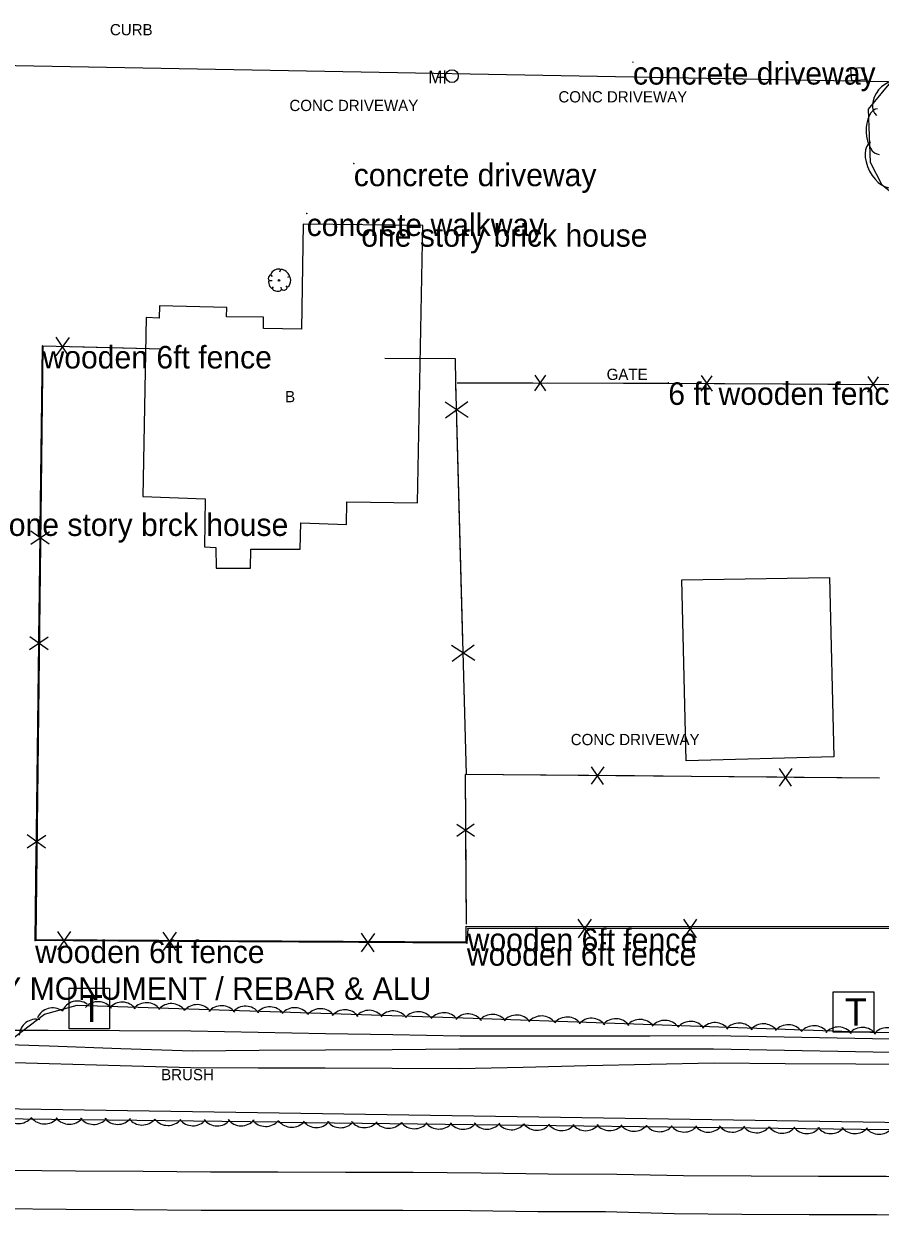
# Model space of a CAD drawing. Extents: x 1802180 to 1804859, y 572524 to 575172.
# Drawn here: x 1803972.5 to 1804162.6, y 573836.1 to 574101.1 of the extents above; entities that cross this region are included whole.
import ezdxf

# ---------------------------------------------------------------- set-up
doc = ezdxf.new("R2010")
doc.units = 0
for name, color, linetype in [('EX_EDGE_PAVEMENT', 7, 'Continuous'), ('EX_SHOULDER', 7, 'Continuous'), ('S_BASELINE', 7, 'Continuous'), ('S_BUILDING', 7, 'Continuous'), ('S_BUILDING_ANNOT', 7, 'Continuous'), ('S_CURB_ANNOT', 7, 'Continuous'), ('S_DITCHLINE', 7, 'Continuous'), ('S_DRIVEWAY_ANNOT', 7, 'Continuous'), ('S_FENCE', 7, 'Continuous'), ('S_FENCE_ANNOT', 7, 'Continuous'), ('S_GATE_ANNOT', 7, 'Continuous'), ('S_IRON_PIN_ANNOT', 7, 'Continuous'), ('S_MANHOLE', 7, 'Continuous'), ('S_MISC_STRUCTURES', 7, 'Continuous'), ('S_MSC_PT_SYM', 7, 'Continuous'), ('S_SANITARY_SEWER', 7, 'Continuous'), ('S_SURVEY_TEXT_ANNOT', 7, 'Continuous'), ('S_TELEPHONE_UTILITIES', 7, 'Continuous'), ('S_TREE', 7, 'Continuous'), ('S_TREE_ANNOT', 7, 'Continuous')]:
    doc.layers.add(name, color=color, linetype=linetype)

msp = doc.modelspace()

# ---------------------------------------------------------------- linework, layer by layer
at = {"layer": 'EX_EDGE_PAVEMENT'}
msp.add_lwpolyline([(1804309.46, 573836.06), (1804294.62, 573836.07), (1804279.62, 573836.18), (1804264.56, 573836.24), (1804251.8, 573836.32), (1804236.8, 573836.41), (1804221.75, 573836.49), (1804206.75, 573836.55), (1804191.75, 573836.68), (1804176.84, 573836.64), (1804161.84, 573836.76), (1804146.85, 573836.78), (1804131.85, 573836.88), (1804116.85, 573836.98), (1804101.6, 573837.45), (1804086.6, 573837.48), (1804071.6, 573837.68), (1804056.62, 573837.73), (1804041.62, 573837.76), (1804026.81, 573837.72), (1804011.81, 573837.78), (1803996.81, 573837.87), (1803981.87, 573837.98), (1803966.87, 573838.11)], dxfattribs=at)
at = {"layer": 'EX_SHOULDER'}
msp.add_lwpolyline([(1803968.94, 573846.7), (1803983.93, 573846.57), (1803998.92, 573846.46), (1804013.89, 573846.36), (1804028.84, 573846.32), (1804043.88, 573846.28), (1804058.89, 573846.23), (1804073.98, 573846.14), (1804088.88, 573845.92), (1804104.13, 573845.83), (1804118.91, 573845.51), (1804133.91, 573845.44), (1804148.86, 573845.37), (1804163.92, 573845.38), (1804178.83, 573845.3), (1804193.93, 573845.35), (1804208.89, 573845.23), (1804223.9, 573845.1), (1804238.9, 573845.02), (1804253.9, 573844.93), (1804265.55, 573844.85)], dxfattribs=at)
at = {"layer": 'S_BASELINE'}
msp.add_line((1803445.92, 573868.28), (1804267.05, 573855.8), dxfattribs=at)
at = {"layer": 'S_BUILDING'}
for points in [[(1804059.83, 573994.85), (1804061.04, 574056.36), (1804034.48, 574056.71), (1804034.1, 574033.41), (1804025.68, 574033.53), (1804025.67, 574036.02), (1804017.47, 574036.1), (1804017.5, 574038.16), (1804002.59, 574038.59), (1804002.48, 574035.79), (1803999.64, 574035.95), (1803998.9, 573996.2), (1804012.69, 573995.72), (1804012.54, 573985.07), (1804015.08, 573984.95), (1804015.19, 573980.31), (1804022.81, 573980.35), (1804022.83, 573984.57), (1804033.83, 573984.55), (1804033.96, 573990.4), (1804044.1, 573990.03), (1804044.2, 573995.06), (1804059.83, 573994.85)], [(1804119.48, 573937.55), (1804118.55, 573977.73), (1804151.34, 573978.23), (1804152.27, 573938.42), (1804119.48, 573937.55)]]:
    msp.add_lwpolyline(points, dxfattribs=at)
at = {"layer": 'S_DITCHLINE'}
for points in [[(1804303.17, 573874.14), (1804288.43, 573874.35), (1804273.69, 573874.56), (1804258.95, 573874.77), (1804244.21, 573874.98), (1804230.25, 573875.07), (1804216.29, 573875.16), (1804202.33, 573875.25), (1804188.37, 573875.34), (1804172.66, 573875.63), (1804156.95, 573875.92), (1804141.23, 573876.21), (1804125.52, 573876.5), (1804111.47, 573876.48), (1804097.41, 573876.47), (1804083.36, 573876.45), (1804069.3, 573876.43), (1804054.36, 573876.72), (1804039.42, 573877), (1804024.48, 573877.28), (1804009.54, 573877.56), (1803993.71, 573877.62), (1803977.88, 573877.67), (1803962.04, 573877.72)], [(1804303.51, 573871.36), (1804288.63, 573871.65), (1804273.75, 573871.94), (1804258.87, 573872.23), (1804243.99, 573872.52), (1804230.13, 573872.49), (1804216.28, 573872.46), (1804202.42, 573872.42), (1804188.57, 573872.39), (1804172.82, 573872.69), (1804157.07, 573872.99), (1804141.32, 573873.29), (1804125.57, 573873.59), (1804111.43, 573873.58), (1804097.3, 573873.57), (1804083.17, 573873.56), (1804069.03, 573873.55), (1804054.24, 573873.45), (1804039.46, 573873.35), (1804024.67, 573873.24), (1804009.88, 573873.14), (1803993.98, 573873.67), (1803978.08, 573874.2), (1803962.19, 573874.73)], [(1804304.14, 573868.36), (1804289.15, 573868.64), (1804274.16, 573868.92), (1804259.16, 573869.21), (1804244.17, 573869.49), (1804230.29, 573869.61), (1804216.41, 573869.73), (1804202.54, 573869.85), (1804188.66, 573869.97), (1804172.93, 573870.09), (1804157.2, 573870.2), (1804141.48, 573870.32), (1804125.75, 573870.44), (1804111.6, 573870.13), (1804097.45, 573869.83), (1804083.29, 573869.53), (1804069.14, 573869.23), (1804054.25, 573869.27), (1804039.35, 573869.32), (1804024.46, 573869.36), (1804009.56, 573869.41), (1803993.84, 573869.85), (1803978.11, 573870.3), (1803962.38, 573870.74)]]:
    msp.add_lwpolyline(points, dxfattribs=at)
at = {"layer": 'S_FENCE'}
for p, q in [((1803974.97, 573897.67), (1803976.6, 574029.65)), ((1803982.55, 574031.53), (1803979.55, 574027.46)), ((1803982.45, 574027.39), (1803979.66, 574031.6)), ((1804085.9, 574019.72), (1804088.32, 574023.16)), ((1804085.91, 574023.16), (1804088.31, 574019.72)), ((1804122.85, 574019.62), (1804125.28, 574023.04)), ((1804122.87, 574023.06), (1804125.26, 574019.6)), ((1804159.81, 574019.4), (1804162.24, 574022.82)), ((1804159.83, 574022.84), (1804162.22, 574019.38)), ((1804071.1, 574013.79), (1804065.98, 574017.17)), ((1804066.07, 574013.66), (1804071, 574017.31)), ((1803974.01, 573985.68), (1803978.14, 573988.5)), ((1803974.01, 573985.68), (1803978.14, 573988.5)), ((1803978.1, 573985.63), (1803974.04, 573988.55)), ((1803978.1, 573985.63), (1803974.04, 573988.55)), ((1803973.72, 573962.25), (1803977.85, 573965.07)), ((1803973.72, 573962.25), (1803977.85, 573965.07)), ((1803977.82, 573962.2), (1803973.76, 573965.12)), ((1803977.82, 573962.2), (1803973.76, 573965.12)), ((1804067.53, 573959.68), (1804072.46, 573963.33)), ((1804072.56, 573959.81), (1804067.44, 573963.19)), ((1804101.2, 573936.21), (1804098.44, 573932.35)), ((1804101.16, 573932.33), (1804098.48, 573936.24)), ((1804142.95, 573935.83), (1804140.19, 573931.97)), ((1804142.91, 573931.94), (1804140.22, 573935.85)), ((1804072.46, 573923.53), (1804068.59, 573920.79)), ((1803973.18, 573918.25), (1803977.31, 573921.07)), ((1803973.18, 573918.25), (1803977.31, 573921.07)), ((1803977.28, 573918.2), (1803973.21, 573921.12)), ((1803977.28, 573918.2), (1803973.21, 573921.12)), ((1804068.58, 573923.51), (1804072.48, 573920.81)), ((1804098.39, 573902.4), (1804095.52, 573898.31)), ((1804098.39, 573898.31), (1804095.52, 573902.4)), ((1804098.39, 573902.4), (1804095.52, 573898.31)), ((1804098.39, 573898.31), (1804095.52, 573902.4)), ((1804121.82, 573902.4), (1804118.96, 573898.3)), ((1804121.82, 573898.3), (1804118.96, 573902.4)), ((1804121.82, 573902.4), (1804118.96, 573898.3)), ((1804121.82, 573898.3), (1804118.96, 573902.4)), ((1803982.85, 573899.67), (1803979.95, 573895.59)), ((1803982.85, 573899.67), (1803979.95, 573895.59)), ((1803982.82, 573895.57), (1803979.98, 573899.68)), ((1803982.82, 573895.57), (1803979.98, 573899.68)), ((1804071, 573900.36), (1804070.83, 573897.09)), ((1804186.39, 573900.34), (1804071, 573900.36)), ((1804070.83, 573897.09), (1803974.97, 573897.67)), ((1804006.28, 573899.52), (1804003.39, 573895.45)), ((1804006.28, 573899.52), (1804003.39, 573895.45)), ((1804006.25, 573895.43), (1804003.41, 573899.54)), ((1804006.25, 573895.43), (1804003.41, 573899.54)), ((1804050.28, 573899.26), (1804047.38, 573895.18)), ((1804050.28, 573899.26), (1804047.38, 573895.18)), ((1804050.25, 573895.16), (1804047.41, 573899.28)), ((1804050.25, 573895.16), (1804047.41, 573899.28))]:
    msp.add_line(p, q, dxfattribs=at)
for points in [[(1804003.25, 574028.95), (1803976.65, 574029.6), (1803975.14, 573897.9), (1804070.65, 573897.42), (1804070.63, 573900.9), (1804247.6, 573900.79), (1804382.52, 573900.68), (1804382.22, 574004.01), (1804344.22, 574004.59)], [(1803976.1, 573989.09), (1803976.59, 574029.09)], [(1803976.1, 573989.09), (1803976.59, 574029.09)], [(1804003.25, 574028.95), (1803983.07, 574029.45)], [(1804070.72, 573934.51), (1804068.38, 574021.52), (1804068.26, 574026.81), (1804052.59, 574026.89)], [(1804068.47, 574017.94), (1804068.38, 574021.52), (1804068.26, 574026.81), (1804052.59, 574026.89)], [(1804068.64, 574021.48), (1804115.24, 574021.38), (1804179.5, 574021)], [(1804068.64, 574021.48), (1804085.43, 574021.44)], [(1804088.79, 574021.44), (1804105.59, 574021.4)], [(1804105.59, 574021.4), (1804115.24, 574021.38), (1804122.39, 574021.34)], [(1804125.75, 574021.32), (1804142.54, 574021.22)], [(1804142.54, 574021.22), (1804159.34, 574021.12)], [(1804069.27, 573988.49), (1804068.61, 574013.03)], [(1804069.93, 573963.96), (1804069.27, 573988.49)], [(1803975.8, 573965.09), (1803976.05, 573985.09)], [(1803975.8, 573965.09), (1803976.05, 573985.09)], [(1803975.27, 573921.66), (1803975.76, 573961.66)], [(1803975.27, 573921.66), (1803975.76, 573961.66)], [(1804070.72, 573934.51), (1804070.06, 573959.05)], [(1804162.44, 573933.71), (1804070.47, 573934.55), (1804070.63, 573901.29)], [(1804078.95, 573934.48), (1804070.47, 573934.55), (1804070.52, 573924.06)], [(1804097.92, 573934.3), (1804078.95, 573934.48)], [(1804120.69, 573934.09), (1804101.72, 573934.27)], [(1804139.67, 573933.92), (1804120.69, 573934.09)], [(1804162.44, 573933.71), (1804143.47, 573933.88)], [(1804070.54, 573920.26), (1804070.63, 573901.29)], [(1803974.97, 573897.67), (1803975.22, 573917.66)], [(1803974.97, 573897.67), (1803975.22, 573917.66)], [(1804071, 573900.36), (1804070.83, 573897.09)], [(1804071, 573900.36), (1804070.83, 573897.09)], [(1804094.96, 573900.35), (1804071, 573900.36)], [(1804094.96, 573900.35), (1804071, 573900.36)], [(1804118.96, 573900.35), (1804098.96, 573900.35)], [(1804118.96, 573900.35), (1804098.96, 573900.35)], [(1804162.39, 573900.35), (1804122.39, 573900.35)], [(1804162.39, 573900.35), (1804122.39, 573900.35)], [(1803979.4, 573897.64), (1803974.97, 573897.67)], [(1803979.4, 573897.64), (1803974.97, 573897.67)], [(1804003.4, 573897.49), (1803983.4, 573897.61)], [(1804003.4, 573897.49), (1803983.4, 573897.61)], [(1804046.83, 573897.23), (1804006.83, 573897.47)], [(1804046.83, 573897.23), (1804006.83, 573897.47)], [(1804070.83, 573897.09), (1804050.83, 573897.21)], [(1804070.83, 573897.09), (1804050.83, 573897.21)]]:
    msp.add_lwpolyline(points, dxfattribs=at)
at = {"layer": 'S_MANHOLE'}
for p, q in [((1804065.91, 574087.93), (1804065.91, 574090.76)), ((1804064.33, 574089.33), (1804065.91, 574089.33))]:
    msp.add_line(p, q, dxfattribs=at)
msp.add_circle((1804067.5, 574089.54), 1.42, dxfattribs=at)
at = {"layer": 'S_MISC_STRUCTURES'}
msp.add_lwpolyline([(1804156.09, 574091.31), (1804158.98, 574091.43), (1804159.16, 574088.7), (1804156.3, 574088.52), (1804156.09, 574091.31)], dxfattribs=at)
at = {"layer": 'S_MSC_PT_SYM'}
for points in [[(1804107.68, 574092.66), (1804107.68, 574092.71), (1804107.68, 574092.66), (1804107.63, 574092.66), (1804107.68, 574092.66), (1804107.68, 574092.61), (1804107.68, 574092.66), (1804107.73, 574092.66)], [(1804045.71, 574070.11), (1804045.71, 574070.16), (1804045.71, 574070.11), (1804045.66, 574070.11), (1804045.71, 574070.11), (1804045.71, 574070.06), (1804045.71, 574070.11), (1804045.76, 574070.11)], [(1804035.25, 574059.05), (1804035.25, 574059.1), (1804035.25, 574059.05), (1804035.2, 574059.05), (1804035.25, 574059.05), (1804035.25, 574059), (1804035.25, 574059.05), (1804035.3, 574059.05)], [(1804047.37, 574056.68), (1804047.37, 574056.73), (1804047.37, 574056.68), (1804047.32, 574056.68), (1804047.37, 574056.68), (1804047.37, 574056.63), (1804047.37, 574056.68), (1804047.42, 574056.68)], [(1803976.6, 574029.65), (1803976.6, 574029.7), (1803976.6, 574029.65), (1803976.55, 574029.65), (1803976.6, 574029.65), (1803976.6, 574029.6), (1803976.6, 574029.65), (1803976.65, 574029.65)], [(1804115.54, 574021.57), (1804115.54, 574021.62), (1804115.54, 574021.57), (1804115.49, 574021.57), (1804115.54, 574021.57), (1804115.54, 574021.52), (1804115.54, 574021.57), (1804115.59, 574021.57)], [(1804071, 573900.36), (1804071, 573900.41), (1804071, 573900.36), (1804070.95, 573900.36), (1804071, 573900.36), (1804071, 573900.31), (1804071, 573900.36), (1804071.05, 573900.36)], [(1803974.97, 573897.67), (1803974.97, 573897.72), (1803974.97, 573897.67), (1803974.92, 573897.67), (1803974.97, 573897.67), (1803974.97, 573897.62), (1803974.97, 573897.67), (1803975.02, 573897.67)], [(1804070.83, 573897.09), (1804070.83, 573897.14), (1804070.83, 573897.09), (1804070.78, 573897.09), (1804070.83, 573897.09), (1804070.83, 573897.04), (1804070.83, 573897.09), (1804070.88, 573897.09)]]:
    msp.add_lwpolyline(points, dxfattribs=at)
at = {"layer": 'S_SANITARY_SEWER'}
msp.add_line((1804440.94, 574083.26), (1803703, 574096.66), dxfattribs=at)
at = {"layer": 'S_TELEPHONE_UTILITIES'}
for points in [[(1803982.51, 573878.1), (1803982.51, 573887.1), (1803991.51, 573887.1), (1803991.51, 573878.1)], [(1804152.17, 573877.31), (1804152.17, 573886.31), (1804161.17, 573886.31), (1804161.17, 573877.31)]]:
    msp.add_lwpolyline(points, close=True, dxfattribs=at)
at = {"layer": 'S_TREE'}
for p, q in [((1804029.41, 574046.53), (1804029.2, 574046.06)), ((1804026.95, 574044.14), (1804027.57, 574044.14)), ((1804027.32, 574045.42), (1804027.6, 574045.1)), ((1804030.95, 574042.73), (1804030.7, 574042.96)), ((1804031.38, 574045), (1804031.02, 574044.85)), ((1804027.6, 574042.39), (1804027.85, 574042.77)), ((1804029.63, 574042.24), (1804029.58, 574042.67))]:
    msp.add_line(p, q, dxfattribs=at)
for points in [[(1804160, 574082.23), (1804167.37, 574091.19), (1804174.59, 574095.48), (1804181.36, 574095.96), (1804189.16, 574095.57), (1804196.27, 574093.31), (1804202.85, 574089.16), (1804206.81, 574083.97), (1804207.81, 574078.01), (1804205.43, 574072.62), (1804199.38, 574067.58), (1804189.26, 574061.55), (1804182.4, 574058.23), (1804174.66, 574058.4), (1804168.52, 574060.89), (1804163.06, 574065.31), (1804160.45, 574070.35), (1804160, 574082.23)], [(1804028.96, 573857.37), (1803940.77, 573858.42), (1803923.97, 573858.58), (1803910.57, 573858.02), (1803901.91, 573857.92), (1803900.12, 573861.4), (1803900.53, 573864.85), (1803905.76, 573869.1), (1803923.73, 573869.56), (1803952.28, 573870.21), (1803968.67, 573874.97), (1803977.07, 573881.31), (1803984.3, 573883.33), (1804072.24, 573880.43), (1804160.36, 573877.32), (1804264.02, 573876.11), (1804344.36, 573877.6), (1804365.24, 573878.46), (1804390.61, 573879.39), (1804413.82, 573880.66), (1804429.89, 573881.62), (1804461.37, 573882.29), (1804473.87, 573881.54)], [(1804491.81, 573853.7), (1804252.68, 573855.92), (1804176.89, 573855.49), (1804029.05, 573857.29)]]:
    msp.add_lwpolyline(points, dxfattribs=at)
msp.add_circle((1804029.11, 574044.19), 0.188, dxfattribs=at)
for centre, radius, start, end in [((1803984.37, 573880.55), 3.7, 54.8697, 156.4666), ((1803988.94, 573880.4), 3.7, 37.3122, 138.9091), ((1803994.3, 573880.3), 3.7, 37.3122, 138.9091), ((1803999.68, 573880.16), 3.7, 37.3122, 138.9091), ((1803978.85, 573879.03), 3.7, 54.8697, 156.4666), ((1804005.2, 573879.98), 3.7, 37.3122, 138.9091), ((1804010.92, 573879.75), 3.7, 37.3122, 138.9091), ((1804016.33, 573879.5), 3.7, 37.3122, 138.9091), ((1804021.69, 573879.4), 3.7, 37.3122, 138.9091), ((1804027.07, 573879.26), 3.7, 37.3122, 138.9091), ((1804032.59, 573879.07), 3.7, 37.3122, 138.9091), ((1804038.32, 573878.85), 3.7, 37.3122, 138.9091), ((1804043.73, 573878.6), 3.7, 37.3122, 138.9091), ((1804049.09, 573878.49), 3.7, 37.3122, 138.9091), ((1804054.47, 573878.35), 3.7, 37.3122, 138.9091), ((1804059.99, 573878.17), 3.7, 37.3122, 138.9091), ((1804065.71, 573877.95), 3.7, 37.3122, 138.9091), ((1804071.12, 573877.69), 3.7, 37.3122, 138.9091), ((1804076.47, 573877.58), 3.7, 37.1767, 138.7736), ((1804081.85, 573877.43), 3.7, 37.1767, 138.7736), ((1803975.14, 573876.51), 3.7, 76.2392, 177.8361), ((1804087.37, 573877.23), 3.7, 37.1767, 138.7736), ((1804093.1, 573876.99), 3.7, 37.1767, 138.7736), ((1804098.51, 573876.73), 3.7, 37.1767, 138.7736), ((1804103.87, 573876.61), 3.7, 37.1767, 138.7736), ((1804109.25, 573876.46), 3.7, 37.1767, 138.7736), ((1804114.77, 573876.26), 3.7, 37.1767, 138.7736), ((1804120.49, 573876.02), 3.7, 37.1767, 138.7736), ((1804125.9, 573875.76), 3.7, 37.1767, 138.7736), ((1804131.26, 573875.64), 3.7, 37.1767, 138.7736), ((1804136.64, 573875.49), 3.7, 37.1767, 138.7736), ((1804142.16, 573875.29), 3.7, 37.1767, 138.7736), ((1804147.88, 573875.06), 3.7, 37.1767, 138.7736), ((1804153.29, 573874.79), 3.7, 37.1767, 138.7736), ((1804158.65, 573874.68), 3.7, 37.1767, 138.7736), ((1804164.1, 573874.61), 3.7, 38.533, 140.1299), ((1803971.31, 573860.76), 3.7, 218.5213, 320.1182), ((1803977.04, 573860.66), 3.7, 218.5213, 320.1182), ((1803982.56, 573860.59), 3.7, 218.5213, 320.1182), ((1803987.95, 573860.56), 3.7, 218.5213, 320.1182), ((1803993.31, 573860.57), 3.7, 218.5213, 320.1182), ((1803998.72, 573860.43), 3.7, 218.5213, 320.1182), ((1804004.45, 573860.33), 3.7, 218.5213, 320.1182), ((1804009.97, 573860.26), 3.7, 218.5213, 320.1182), ((1804015.36, 573860.24), 3.7, 218.5213, 320.1182), ((1804020.72, 573860.25), 3.7, 218.5213, 320.1182), ((1804026.13, 573860.11), 3.7, 218.5213, 320.1182), ((1804031.93, 573859.9), 3.67, 218.5055, 320.1024), ((1804037.41, 573859.83), 3.67, 218.5055, 320.1024), ((1804042.76, 573859.8), 3.67, 218.5055, 320.1024), ((1804048.08, 573859.81), 3.67, 218.5055, 320.1024), ((1804053.46, 573859.67), 3.67, 218.5055, 320.1024), ((1804059.15, 573859.57), 3.67, 218.5055, 320.1024), ((1804064.63, 573859.5), 3.67, 218.5055, 320.1024), ((1804069.98, 573859.47), 3.67, 218.5055, 320.1024), ((1804075.3, 573859.48), 3.67, 218.5055, 320.1024), ((1804080.68, 573859.34), 3.67, 218.5055, 320.1024), ((1804086.37, 573859.24), 3.67, 218.5055, 320.1024), ((1804091.85, 573859.17), 3.67, 218.5055, 320.1024), ((1804097.2, 573859.14), 3.67, 218.5055, 320.1024), ((1804102.52, 573859.15), 3.67, 218.5055, 320.1024), ((1804107.9, 573859.01), 3.67, 218.5055, 320.1024), ((1804113.59, 573858.91), 3.67, 218.5055, 320.1024), ((1804119.07, 573858.84), 3.67, 218.5055, 320.1024), ((1804124.42, 573858.81), 3.67, 218.5055, 320.1024), ((1804129.74, 573858.82), 3.67, 218.5055, 320.1024), ((1804135.12, 573858.68), 3.67, 218.5055, 320.1024), ((1804140.81, 573858.58), 3.67, 218.5055, 320.1024), ((1804146.29, 573858.51), 3.67, 218.5055, 320.1024), ((1804151.64, 573858.48), 3.67, 218.5055, 320.1024), ((1804156.96, 573858.49), 3.67, 218.5055, 320.1024), ((1804162.34, 573858.35), 3.67, 218.5055, 320.1024)]:
    msp.add_arc(centre, radius, start, end, dxfattribs=at)
for centre, major_axis, ratio, start_param, end_param in [((1804164.72, 574084.42), (-2.98, -3.62), 0.685311, 3.141593, 6.283185), ((1804162.2, 574077.24), (0.19, -5.06), 0.540699, 3.141593, 6.283185), ((1804162.96, 574069.88), (2.56, -4.93), 0.55008, 3.141593, 6.283185), ((1804028.37, 574045.96), (1.02, 0.6), 0.471018, 0, 3.141593), ((1804030.38, 574045.78), (-1, 0.75), 0.405113, 3.141593, 6.283186), ((1804027.14, 574044.79), (0.168, 0.567), 0.646762, 0, 3.141593), ((1804027.3, 574043.33), (-0.337, 0.88), 0.420543, 6.283185, 9.424777), ((1804031.13, 574043.9), (0.25, 1.13), 0.482994, 3.141593, 6.283185), ((1804028.66, 574042.35), (-1.01, 0.11), 0.529943, 0, 3.141593), ((1804030.29, 574042.51), (0.602, 0.255), 0.711534, 3.141592, 6.283185)]:
    msp.add_ellipse(centre, major_axis=major_axis, ratio=ratio, start_param=start_param, end_param=end_param, dxfattribs=at)

# ---------------------------------------------------------------- texts
at = {"layer": 'S_BUILDING_ANNOT'}
msp.add_text('B', height=2.5, dxfattribs=at).set_placement((1804030.46, 574017.15))
at = {"layer": 'S_CURB_ANNOT'}
msp.add_text('CURB', height=2.5, dxfattribs=at).set_placement((1803991.57, 574098.6))
at = {"layer": 'S_DRIVEWAY_ANNOT'}
for p in [(1804091.14, 574083.7), (1804031.42, 574081.78), (1804093.88, 573941.04)]:
    msp.add_text('CONC DRIVEWAY', height=2.5, dxfattribs=at).set_placement(p)
at = {"layer": 'S_FENCE_ANNOT'}
for p in [(1803976.6, 574024.65), (1804071, 573895.36), (1803974.97, 573892.67), (1804070.83, 573892.09)]:
    msp.add_text('wooden 6ft fence ', height=5, dxfattribs=at).set_placement(p)
at = {"layer": 'S_GATE_ANNOT'}
msp.add_text('GATE', height=2.5, dxfattribs=at).set_placement((1804101.85, 574022.1))
at = {"layer": 'S_IRON_PIN_ANNOT'}
msp.add_text('BOUNDARY MONUMENT / REBAR & ALU ', height=5, dxfattribs=at).set_placement((1803933.99, 573884.51))
at = {"layer": 'S_MANHOLE'}
msp.add_text('M', height=2.82, dxfattribs=at).set_placement((1804062.25, 574087.96))
at = {"layer": 'S_SURVEY_TEXT_ANNOT'}
for s, p in [('concrete driveway', (1804107.68, 574087.66)), ('concrete driveway', (1804045.71, 574065.11)), ('concrete walkway', (1804035.25, 574054.05)), ('one story brick house', (1804047.37, 574051.68)), ('6 ft wooden fence', (1804115.54, 574016.57)), ('one story brck house', (1803969.11, 573987.48))]:
    msp.add_text(s, height=5, dxfattribs=at).set_placement(p)
at = {"layer": 'S_TELEPHONE_UTILITIES'}
for p in [(1803985.08, 573879.6), (1804154.74, 573878.81)]:
    msp.add_text('T', height=6, rotation=360, dxfattribs=at).set_placement(p)
at = {"layer": 'S_TREE_ANNOT'}
msp.add_text('BRUSH', height=2.5, dxfattribs=at).set_placement((1804002.94, 573866.66))

doc.saveas('drawing.dxf')
